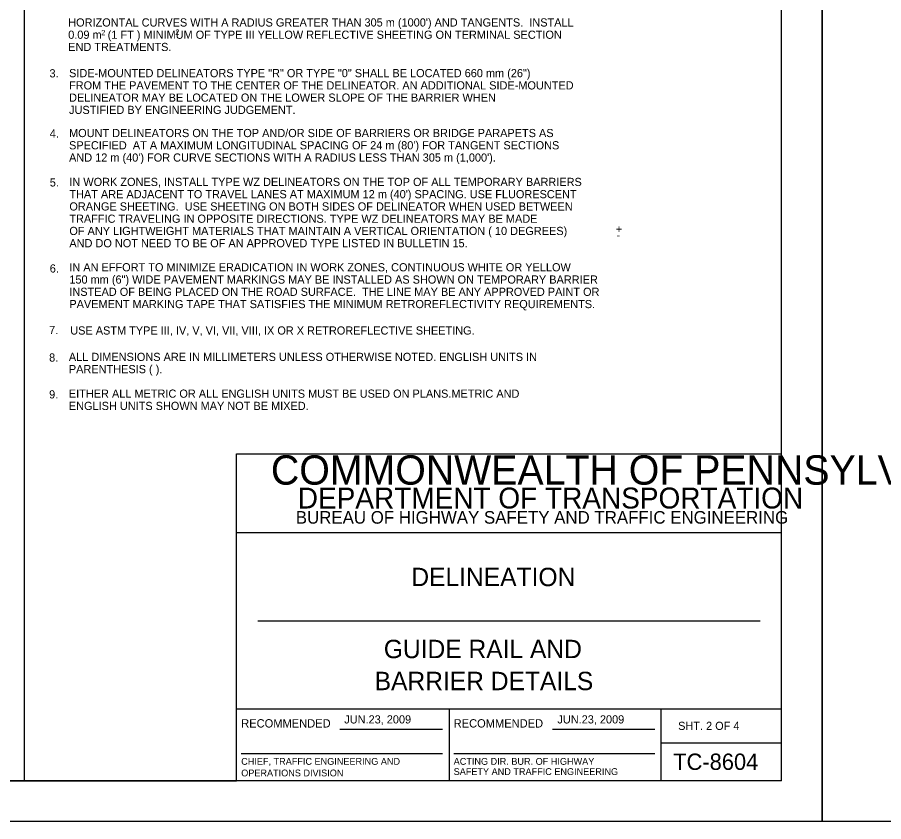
# Model space of a CAD drawing. Extents: x 640253 to 641999, y 298458 to 299646.
# Drawn here: x 640798.8 to 641116.9, y 298457.6 to 298753 of the extents above; entities that cross this region are included whole.
import ezdxf

# ---------------------------------------------------------------- set-up
doc = ezdxf.new("R2010")
doc.units = 0
for name, color, linetype in [('1', 7, 'Continuous'), ('2', 7, 'Continuous'), ('PLT-BNDY', 7, 'Continuous')]:
    doc.layers.add(name, color=color, linetype=linetype)

msp = doc.modelspace()

# ---------------------------------------------------------------- linework, layer by layer
at = {"layer": '1'}
for p, q in [((640801.38, 298472.63), (640801.38, 299036.63)), ((641079.31, 298472.63), (641079.31, 299036.63)), ((640879.31, 298472.63), (640879.31, 298592.63)), ((640879.31, 298592.63), (641079.31, 298592.63)), ((641079.31, 298563.63), (640879.31, 298563.63)), ((640887.06, 298531.31), (641071.56, 298531.31)), ((640879.31, 298499), (641079.31, 298499)), ((640957.31, 298499), (640957.31, 298472.63)), ((641035.19, 298472.63), (641035.19, 298499)), ((640917.24, 298491.57), (640954.87, 298491.57)), ((640995.24, 298491.57), (641032.87, 298491.57)), ((641035.19, 298486.63), (641079.31, 298486.63)), ((640880.99, 298482.68), (640954.87, 298482.68)), ((640958.99, 298482.68), (641032.87, 298482.68)), ((641079.31, 298472.63), (640293.31, 298472.63)), ((640293.31, 298472.63), (640879.31, 298472.63))]:
    msp.add_line(p, q, dxfattribs=at)
at = {"layer": 'PLT-BNDY'}
for points in [[(640253.31, 299051.63), (641094.31, 299051.63), (641094.31, 298457.63), (640253.31, 298457.63)], [(641094.31, 299051.63), (641935.31, 299051.63), (641935.31, 298457.63), (641094.31, 298457.63)]]:
    msp.add_lwpolyline(points, close=True, dxfattribs=at)

# ---------------------------------------------------------------- texts
at = {"layer": '1'}
for s, height, p in [('COMMONWEALTH OF PENNSYLVANIA', 10.7828, (640891.9, 298581.36)), ('DEPARTMENT OF TRANSPORTATION', 7.6837, (640901.76, 298572.61)), ('BUREAU OF HIGHWAY SAFETY AND TRAFFIC ENGINEERING', 4.6253, (640901.04, 298567.04)), ('DELINEATION', 6.75, (640943.46, 298544.1)), ('GUIDE RAIL AND', 6.75, (640933.34, 298517.66)), ('BARRIER DETAILS', 6.75, (640929.99, 298505.91)), ('RECOMMENDED', 3.048, (640880.99, 298492.2)), ('JUN.23, 2009', 3, (640918.83, 298493.69)), ('RECOMMENDED', 3.048, (640958.99, 298492.2)), ('JUN.23, 2009', 3, (640997.08, 298493.69)), ('SHT. 2 OF 4', 3, (641041.4, 298491.31)), ('TC-8604', 6, (641039.6, 298476.63)), ('CHIEF, TRAFFIC ENGINEERING AND', 2.5, (640880.99, 298478.51)), ('ACTING DIR. BUR. OF HIGHWAY', 2.5, (640958.99, 298478.51)), ('OPERATIONS DIVISION', 2.5, (640880.99, 298474.26)), ('SAFETY AND TRAFFIC ENGINEERING', 2.5, (640958.99, 298474.76))]:
    msp.add_text(s, height=height, dxfattribs=at).set_placement(p)
at = {"layer": '2'}
for s, height, p in [("HORIZONTAL CURVES WITH A RADIUS GREATER THAN 305 m (1000') AND TANGENTS.  INSTALL", 3, (640817.48, 298749.57)), ('0.09 m  (1 FT ) MINIMUM OF TYPE III YELLOW REFLECTIVE SHEETING ON TERMINAL SECTION', 3, (640817.48, 298745.07)), ('2', 2, (640829.57, 298746.32)), ('2', 2, (640856.8, 298746.5)), ('END TREATMENTS.', 3, (640817.48, 298740.57)), ('3.', 3, (640810.61, 298730.89)), ('SIDE-MOUNTED DELINEATORS TYPE "R" OR TYPE "0" SHALL BE LOCATED 660 mm (26") ', 3, (640817.79, 298730.97)), ('FROM THE PAVEMENT TO THE CENTER OF THE DELINEATOR. AN ADDITIONAL SIDE-MOUNTED ', 3, (640817.79, 298726.47)), ('DELINEATOR MAY BE LOCATED ON THE LOWER SLOPE OF THE BARRIER WHEN ', 3, (640817.79, 298721.97)), ('JUSTIFIED BY ENGINEERING JUDGEMENT.', 3, (640817.79, 298717.47)), ('4.', 3, (640810.71, 298708.82)), ('MOUNT DELINEATORS ON THE TOP AND/OR SIDE OF BARRIERS OR BRIDGE PARAPETS AS ', 3, (640817.79, 298708.97)), ("SPECIFIED  AT A MAXIMUM LONGITUDINAL SPACING OF 24 m (80') FOR TANGENT SECTIONS ", 3, (640817.79, 298704.47)), ("AND 12 m (40') FOR CURVE SECTIONS WITH A RADIUS LESS THAN 305 m (1,000').", 3, (640817.79, 298699.97)), ('5.', 3, (640810.71, 298690.84)), ('IN WORK ZONES, INSTALL TYPE WZ DELINEATORS ON THE TOP OF ALL TEMPORARY BARRIERS', 3, (640817.9, 298691.02)), ("THAT ARE ADJACENT TO TRAVEL LANES AT MAXIMUM 12 m (40') SPACING. USE FLUORESCENT ", 3, (640817.9, 298686.52)), ('ORANGE SHEETING.  USE SHEETING ON BOTH SIDES OF DELINEATOR WHEN USED BETWEEN', 3, (640817.9, 298682.02)), ('TRAFFIC TRAVELING IN OPPOSITE DIRECTIONS. TYPE WZ DELINEATORS MAY BE MADE', 3, (640817.9, 298677.52)), ('+', 3, (641018.54, 298673.75)), ('OF ANY LIGHTWEIGHT MATERIALS THAT MAINTAIN A VERTICAL ORIENTATION ( 10 DEGREES) ', 3, (640817.9, 298673.02)), ('AND DO NOT NEED TO BE OF AN APPROVED TYPE LISTED IN BULLETIN 15.', 3, (640817.9, 298668.52)), ('-', 3, (641018.75, 298671.51)), ('6.', 3, (640810.71, 298659.24)), ('IN AN EFFORT TO MINIMIZE ERADICATION IN WORK ZONES, CONTINUOUS WHITE OR YELLOW ', 3, (640817.9, 298659.68)), ('150 mm (6") WIDE PAVEMENT MARKINGS MAY BE INSTALLED AS SHOWN ON TEMPORARY BARRIER ', 3, (640817.9, 298655.18)), ('INSTEAD OF BEING PLACED ON THE ROAD SURFACE.  THE LINE MAY BE ANY APPROVED PAINT OR ', 3, (640817.9, 298650.68)), ('PAVEMENT MARKING TAPE THAT SATISFIES THE MINIMUM RETROREFLECTIVITY REQUIREMENTS.', 3, (640817.9, 298646.18)), ('7.', 3, (640810.47, 298636.64)), ('USE ASTM TYPE III, IV, V, VI, VII, VIII, IX OR X RETROREFLECTIVE SHEETING.', 3, (640818.23, 298636.47)), ('8.', 3, (640810.47, 298626.55)), ('ALL DIMENSIONS ARE IN MILLIMETERS UNLESS OTHERWISE NOTED. ENGLISH UNITS IN ', 3, (640817.72, 298626.78)), ('PARENTHESIS ( ).', 3, (640817.72, 298622.28)), ('9.', 3, (640810.47, 298613.02)), ('EITHER ALL METRIC OR ALL ENGLISH UNITS MUST BE USED ON PLANS.METRIC AND ', 3, (640817.72, 298613.28)), ('ENGLISH UNITS SHOWN MAY NOT BE MIXED.', 3, (640817.72, 298608.78))]:
    msp.add_text(s, height=height, dxfattribs=at).set_placement(p)

doc.saveas('drawing.dxf')
